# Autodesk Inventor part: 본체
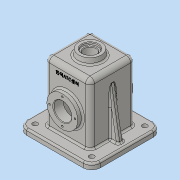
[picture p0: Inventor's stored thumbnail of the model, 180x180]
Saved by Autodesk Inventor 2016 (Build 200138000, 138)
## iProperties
Created: 2022-11
Part Number: 본체
Material: 일반
Document SubType Name: Modeling
Designer: 하동건
Density: 1 g/cm^3
Appearance: 기본값
Author: 하동건
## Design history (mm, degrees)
sketch "스케치1"
  geometry: L1 (40, -40)-(-40, -40); L2 (-40, -40)-(-40, 40); L3 (-40, 40)-(40, 40); L4 (40, 40)-(40, -40); L5 (40, -40)-(-40, 40); L6 (-40, -40)-(40, 40); 1 further point
  constraints: 12 end point, 2 midpoint, 2 parallel, 1 horizontal, 1 perpendicular
  dimensions: "d0" = 80 distance of L2.end L3.end; "d1" = 80 distance of L3.end L1.start
extrude "돌출1" new body sketch "스케치1" distance "d2" = 107; taper "d3" = 0 deg
sketch "스케치2"
  geometry: L1 (-65, 62)-(65, 62); L2 (65, 62)-(65, -62); L3 (65, -62)-(-65, -62); L4 (-65, -62)-(-65, 62); L5 (-65, 62)-(65, -62); L6 (65, 62)-(-65, -62); 1 further point
  constraints: 12 end point, 2 midpoint, 2 parallel, 1 horizontal, 1 perpendicular
  dimensions: "d4" = 130 distance of L2.end L3.end; "d5" = 124 distance of L3.end L1.start
extrude "돌출2" join sketch "스케치2" distance "d6" = 10; taper "d7" = 0 deg
sketch "스케치3"
  geometry: L1 (-32, 32)-(32, 32); L2 (32, 32)-(32, -32); L3 (32, -32)-(-32, -32); L4 (-32, -32)-(-32, 32); L5 (-32, 32)-(32, -32); L6 (32, 32)-(-32, -32); 1 further point
  constraints: 12 end point, 2 midpoint, 2 parallel, 1 horizontal, 1 perpendicular
  dimensions: "d9" = 64 distance of L2.end L3.end; "d10" = 64 distance of L3.end L1.start
extrude "돌출3" cut sketch "스케치3" distance "d11" = 109; taper "d12" = 0 deg
node "작업 평면1"
sketch "스케치4"
  geometry: L1 (65, -117)-(-65, -117) reference; L2 (0, -117)-(0, -62); C1 r 27.5 at (0, -62); 1 further point
  constraints: 2 end point, 1 centre point, 1 coincident, 1 midpoint, 1 vertical
  dimensions: "d14" = 55 distance of L2.start L2.end; "d15" = 55 diameter of C1
extrude "돌출4" join sketch "스케치4" stored distance "d16" = 109; taper "d17" = 0 deg
sketch "스케치5"
  geometry: C1 r 27.5 at (0, 0) reference; C2 r 16 at (0, 0); 1 further point
  constraints: 1 centre point, 1 coincident
  dimensions: "d18" = 32 diameter of C2
extrude "돌출5" cut sketch "스케치5" stored distance "d19" = 109; taper "d20" = 0 deg
fillet "모깎기1" dims "d21" = 15
sketch "스케치7"
  geometry: L1 (0, 0)-(0, 22.5); C1 r 27.5 at (0, 0) reference; 1 further point
  constraints: 2 end point, 1 vertical
  dimensions: "d22" = 22.5 distance of L1.start L1.end
hole "구멍1" sketch "스케치7" at (0, 22.5) diameter "d23" = 3.242; stored, may be unused: countersink angle "d27" = 90 deg, drill point angle "d29" = 118 deg; dims "d24" = 8, "d25" = 4, "d26" = 2, "d28" = 10
fillet "모깎기2" dims "d33" = 8
fillet "모깎기3" dims "d34" = 8
fillet "모깎기5" dims "d36" = 3
chamfer "모따기1" distance "d37" = 1; stored, may be unused: second distance "d38" = 2, angle "d39" = 45 deg
fillet "모깎기6" dims "d40" = 3
fillet "모깎기7" dims "d41" = 3
node "작업 평면2"
sketch "스케치8"
  geometry: C1 r 20 at (0, 0); 1 further point
  constraints: 1 centre point, 1 coincident
  dimensions: "d43" = 40 diameter of C1
extrude "돌출6" join sketch "스케치8" stored distance "d44" = 109; taper "d45" = 10 deg
sketch "스케치9"
  geometry: C1 r 14 at (0, 0); 1 further point
  constraints: 1 centre point, 1 coincident
  dimensions: "d46" = 28 diameter of C1
extrude "돌출7" cut sketch "스케치9" distance "d47" = 4; taper "d48" = 0 deg
sketch "스케치10"
  geometry: C1 r 10.5 at (0, 0); 1 further point
  constraints: 1 centre point, 1 coincident
  dimensions: "d49" = 21 diameter of C1
extrude "돌출8" cut sketch "스케치10" stored distance "d50" = 4; taper "d51" = 0 deg
chamfer "모따기2" distance "d52" = 1; stored, may be unused: second distance "d53" = 2, angle "d54" = 45 deg
sketch "스케치12"
  geometry: L1 (-65, -107)-(-50, -107) reference; L2 (-55, -107)-(-48.092, -67.82); L3 (-65, -107)-(-65, -117) reference; 1 further point
  constraints: 2 end point, 1 point on line
  dimensions: "d62" = 100 deg angle of L1 L2; "d63" = 10 distance from line of L2.start L3
feature "리브2" sketch "스케치12" dims "d64" = 1, "d65" = 10, "d66" = 0, "d67" = 0, "d68" = 1, "d69" = 1
fillet "모깎기8" dims "d70" = 3
fillet "모깎기9" dims "d71" = 3
fillet "모깎기10" dims "d72" = 3
fillet "모깎기11" dims "d73" = 3
fillet "모깎기12" dims "d74" = 3
fillet "모깎기13" dims "d75" = 3
sketch "스케치13"
  geometry: A1 r 15 centre (-50, 47) between (-50, 62) and (-65, 47) reference; A2 r 15 centre (50, 47) between (65, 47) and (50, 62) reference; A3 r 15 centre (-50, -47) between (-65, -47) and (-50, -62) reference; A4 r 15 centre (50, -47) between (50, -62) and (65, -47) reference; 1 further point
hole "구멍2" sketch "스케치13" at (-50, -47), (50, -47), (50, 47), (-50, 47) diameter "d76" = 9; stored, may be unused: countersink angle "d80" = 90 deg, drill point angle "d82" = 118 deg; dims "d77" = 8, "d78" = 4, "d79" = 2, "d81" = 10
node "작업 평면3"
sketch "스케치14"
  geometry: L1 (40, -104)-(40, -8) reference; L2 (20, 10)-(-20, 10) reference; 2 further points
  constraints: 1 other
  dimensions: "d84" = 40 distance from line of L1 point (0, -15); "d85" = 25 distance from line of L2 point (0, -15)
feature "엠보싱1" sketch "스케치14" dims "d9" = 64, "d10" = 64, "d86" = 0.5, "d87" = 0
feature "분할1"
node "솔리드1"
mirror "대칭1"
pattern_circular "원형 패턴1" dims angle "d31" = 360 deg
mirror "대칭2"
mirror "대칭4"
node "투영된 루프1"
other parameters: "d13" = -49, "d42" = -127, "d83" = -53.75
